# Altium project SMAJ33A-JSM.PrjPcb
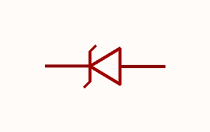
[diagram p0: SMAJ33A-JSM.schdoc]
1 sheet, 1 parts. Net scope: global (net labels, ports and power ports of the same name join across sheets).

## Sheet SMAJ33A-JSM.schdoc
size 127 x 101 mm

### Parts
D?  smaj33a-jsm  [SMA_L4.3-W2.6-LS5.2-RD]  (value not drawn)

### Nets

Not connected (* = marked no-connect by the designer): D? 1(C) 2(A)

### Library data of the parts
D? = smaj33a-jsm: 极性:单向;反向截止电压(Vrwm):33V;钳位电压:53.3V;峰值脉冲电流(Ipp):7.5A;峰值脉冲功率(Ppp):400W;击穿电压(VBR):40.6V;; Manufacturer: JSMSEMI(杰盛微); AddInBom: yes; ModelId: e3551acb3c5a4975a5e9d36087fe1fa2; ModelTransform: 185.039,102.362,0,0,0,0,0,0,0; Polarity: 单向; Reverse Stand-Off Voltage (Vrwm): 33V; Clamping Voltage: 53.3V; Peak Pulse Current (Ipp): 7.5A; Peak Pulse Power Dissipation (Ppp): 400W; Voltage - Breakdown: 40.6V; Reverse Leakage Current (Ir): 1uA; Number of Channels: 单路; Type: TVS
